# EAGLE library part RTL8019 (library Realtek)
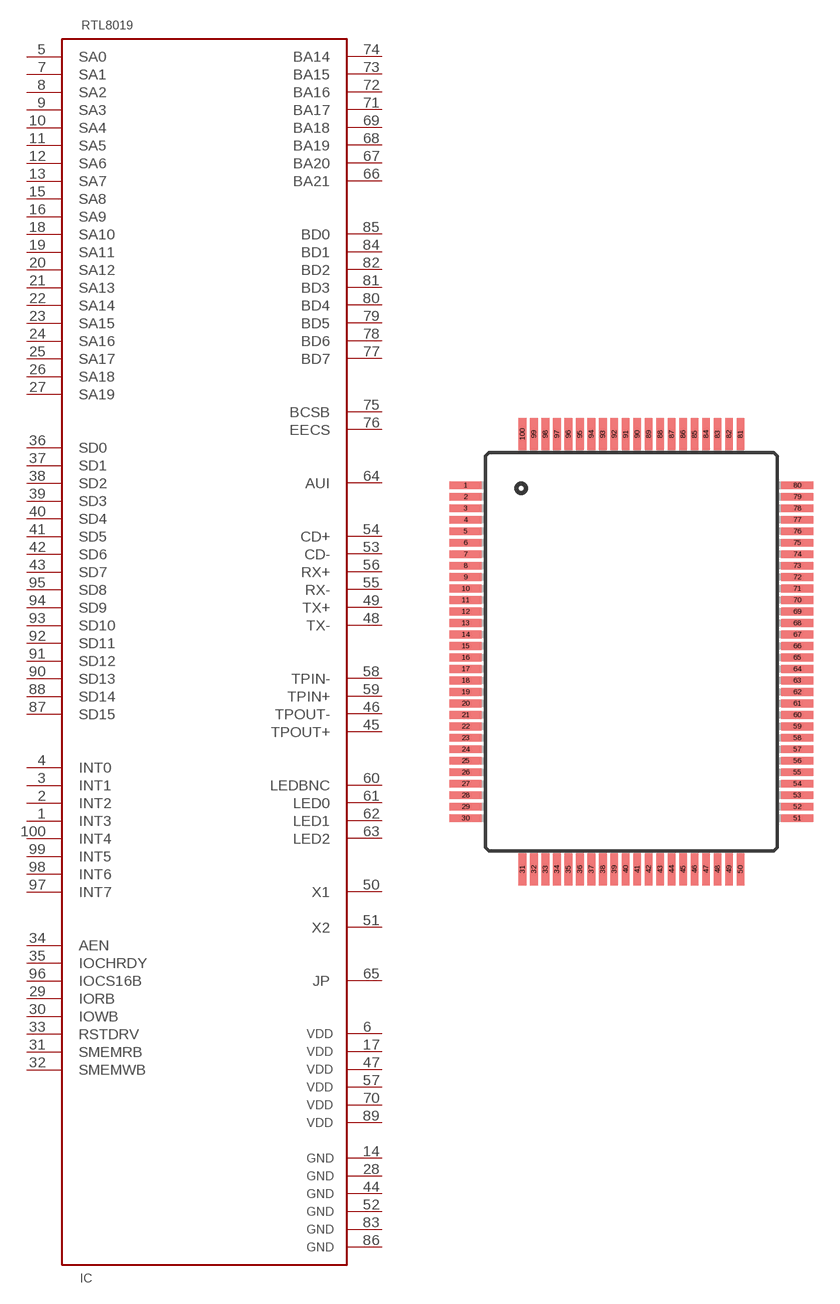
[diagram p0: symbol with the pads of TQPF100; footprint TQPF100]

Designator prefix IC

## RTL8019  [TQPF100]
1  INT3
2  INT2
3  INT1
4  INT0
5  SA0
6  V1  pwr
7  SA1
8  SA2
9  SA3
10  SA4
11  SA5
12  SA6
13  SA7
14  G1  pwr
15  SA8
16  SA9
17  V2  pwr
18  SA10
19  SA11
20  SA12
21  SA13
22  SA14
23  SA15
24  SA16
25  SA17
26  SA18
27  SA19
28  G2  pwr
29  IORB
30  IOWB
31  SMEMRB
32  SMEMWB
33  RSTDRV
34  AEN
35  IOCHRDY
36  SD0
37  SD1
38  SD2
39  SD3
40  SD4
41  SD5
42  SD6
43  SD7
44  G3  pwr
45  TPOUT+
46  TPOUT-
47  V3  pwr
48  TX-
49  TX+
50  X1
51  X2
52  G4  pwr
53  CD-
54  CD+
55  RX-
56  RX+
57  V4  pwr
58  TPIN-
59  TPIN+
60  LEDBNC
61  LED0
62  LED1
63  LED2
64  AUI
65  JP
66  BA21
67  BA20
68  BA19
69  BA18
70  V5  pwr
71  BA17
72  BA16
73  BA15
74  BA14
75  BCSB
76  EECS
77  BD7
78  BD6
79  BD5
80  BD4
81  BD3
82  BD2
83  G5  pwr
84  BD1
85  BD0
86  G6  pwr
87  SD15
88  SD14
89  V6  pwr
90  SD13
91  SD12
92  SD11
93  SD10
94  SD9
95  SD8
96  IOCS16B
97  INT7
98  INT6
99  INT5
100  INT4

## Footprint TQPF100 (pad centres in mm)
smd 1.8 x 0.44: 1 -9.395,9.425; 2 -9.395,8.775; 3 -9.395,8.125; 4 -9.395,7.475; 5 -9.395,6.825; 6 -9.395,6.175; 7 -9.395,5.525; 8 -9.395,4.875; 9 -9.395,4.225; 10 -9.395,3.575; 11 -9.395,2.925; 12 -9.395,2.275; 13 -9.395,1.625; 14 -9.395,0.975; 15 -9.395,0.325; 16 -9.395,-0.325; 17 -9.395,-0.975; 18 -9.395,-1.625; 19 -9.395,-2.275; 20 -9.395,-2.925; 21 -9.395,-3.575; 22 -9.395,-4.225; 23 -9.395,-4.875; 24 -9.395,-5.525; 25 -9.395,-6.175; 26 -9.395,-6.825; 27 -9.395,-7.475; 28 -9.395,-8.125; 29 -9.395,-8.775; 30 -9.395,-9.425; 51 9.395,-9.425; 52 9.395,-8.775; 53 9.395,-8.125; 54 9.395,-7.475; 55 9.395,-6.825; 56 9.395,-6.175; 57 9.395,-5.525; 58 9.395,-4.875; 59 9.395,-4.225; 60 9.395,-3.575; 61 9.395,-2.925; 62 9.395,-2.275; 63 9.395,-1.625; 64 9.395,-0.975; 65 9.395,-0.325; 66 9.395,0.325; 67 9.395,0.975; 68 9.395,1.625; 69 9.395,2.275; 70 9.395,2.925; 71 9.395,3.575; 72 9.395,4.225; 73 9.395,4.875; 74 9.395,5.525; 75 9.395,6.175; 76 9.395,6.825; 77 9.395,7.475; 78 9.395,8.125; 79 9.395,8.775; 80 9.395,9.425
smd 0.44 x 1.8: 31 -6.175,-12.32; 32 -5.525,-12.32; 33 -4.875,-12.32; 34 -4.225,-12.32; 35 -3.575,-12.32; 36 -2.925,-12.32; 37 -2.275,-12.32; 38 -1.625,-12.32; 39 -0.975,-12.32; 40 -0.325,-12.32; 41 0.325,-12.32; 42 0.975,-12.32; 43 1.625,-12.32; 44 2.275,-12.32; 45 2.925,-12.32; 46 3.575,-12.32; 47 4.225,-12.32; 48 4.875,-12.32; 49 5.525,-12.32; 50 6.175,-12.32; 81 6.175,12.32; 82 5.525,12.32; 83 4.875,12.32; 84 4.225,12.32; 85 3.575,12.32; 86 2.925,12.32; 87 2.275,12.32; 88 1.625,12.32; 89 0.975,12.32; 90 0.325,12.32; 91 -0.325,12.32; 92 -0.975,12.32; 93 -1.625,12.32; 94 -2.275,12.32; 95 -2.925,12.32; 96 -3.575,12.32; 97 -4.225,12.32; 98 -4.875,12.32; 99 -5.525,12.32; 100 -6.175,12.32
